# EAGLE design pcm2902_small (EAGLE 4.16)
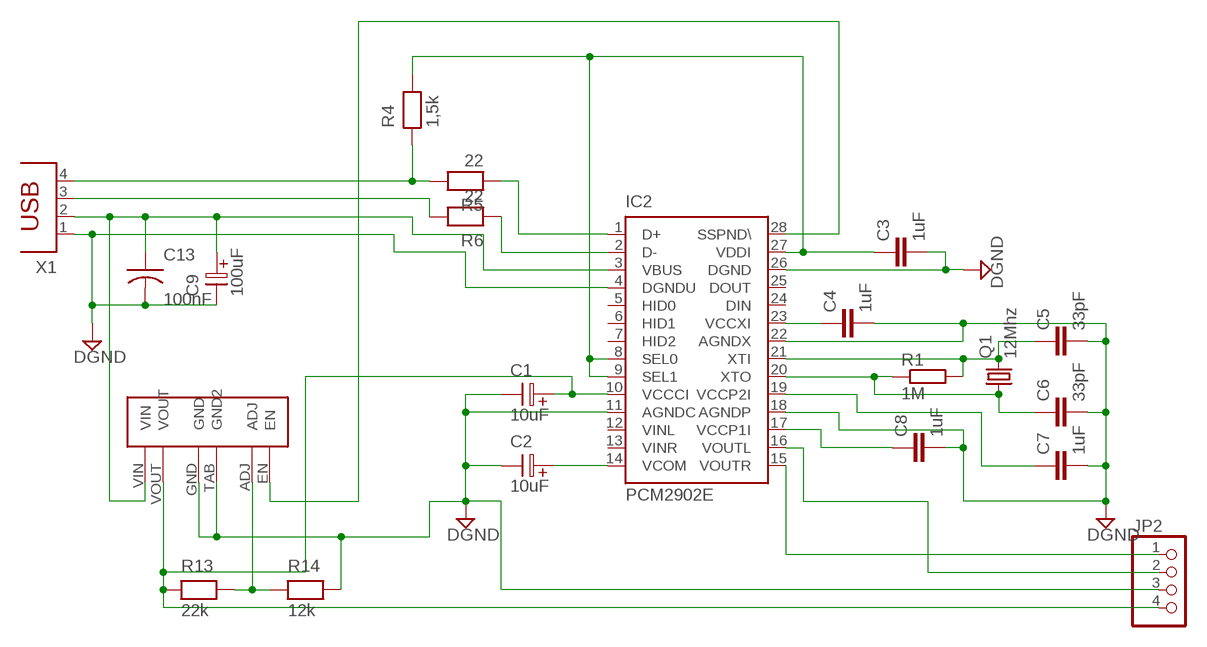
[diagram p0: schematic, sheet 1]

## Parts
C1  10uF  ELC-2,5L  [ES-2,5L]
C2  10uF  ELC-2,5L  [ES-2,5L]
C3  1uF  C-EUC1206  [C1206]
C4  1uF  C-EUC1206  [C1206]
C5  33pF  C-EUC1206  [C1206]
C6  33pF  C-EUC1206  [C1206]
C7  1uF  C-EUC1206  [C1206]
C8  1uF  C-EUC1206  [C1206]
C9  100uF  ELC-2,5L  [ES-2,5L]
C13  100nF  CAP-2,5  [C-2,5]
IC2  PCM2902E  [SSOP28DB]
JP2  PINHD-1X4  [1X04]
Q1  12Mhz  CRYTALHC49U-V  [HC49U-V]
R1  1M  R-EU_R1206  [R1206]
R4  1,5k  RESEU-5  [R-5]
R5  22  RESEU-5  [R-5]
R6  22  RESEU-5  [R-5]
R13  22k  RESEU-5  [R-5]
R14  12k  RESEU-5  [R-5]
U$2  REG102GA-A  [SOT223-5]
X1  PN87520  [PN87520]

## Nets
DGND: C1.2 C2.2 C3.2 C4.2 C5.2 C6.2 C7.2 C8.2 C9.2 C13.2 IC2.4(DGNDU) IC2.11(AGNDC) IC2.18(AGNDP) IC2.22(AGNDX) IC2.26(DGND) JP2.3 R14.2 U$2.GND U$2.TAB(GND2) X1.1
N$1: C2.1 IC2.14(VCOM)
N$2: C1.1 IC2.10(VCCCI) JP2.4 R13.1 U$2.VOUT
N$3: IC2.1(D+) R5.1
N$4: R4.1 R5.2 X1.4
N$5: R6.2 X1.3
N$6: IC2.2(D-) R6.1
N$8: C3.1 IC2.8(SEL0) IC2.9(SEL1) IC2.27(VDDI) R4.2
N$14: C4.1 IC2.23(VCCXI)
N$15: IC2.28(SSPND\) U$2.EN
N$18: C5.1 IC2.21(XTI) Q1.2 R1.2
N$19: C6.1 IC2.20(XTO) Q1.1 R1.1
N$20: C7.1 IC2.19(VCCP2I)
N$21: C8.1 IC2.17(VCCP1I)
N$24: IC2.16(VOUTL) JP2.2
N$25: IC2.15(VOUTR) JP2.1
N$26: R13.2 R14.1 U$2.ADJ
N$30: C9.1 C13.1 IC2.3(VBUS) U$2.VIN X1.2
Unconnected: IC2.5(HID0) IC2.6(HID1) IC2.7(HID2) IC2.12(VINL) IC2.13(VINR) IC2.24(DIN) IC2.25(DOUT)

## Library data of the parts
C1 C2 C9 = discrete:ELC-2,5L
C3-C8 = rcl:C-EU: CAPACITOR, European symbol
C13 = discrete:CAP-2,5
IC2 = texas:PCM290*: STEREO AUDIO CODEC WITH USB INTERFACE SINGLE-ENDED ANALOG INPUT/OUTPUT AND S/PDIF
JP2 = pinhead:PINHD-1X4: PIN HEADER
Q1 = crystal:CRYTAL: CRYSTAL
R1 = rcl:R-EU_: RESISTOR, European symbol
R4-R6 R13 R14 = discrete:RESEU-5
U$2 = Reg102:REG102GA-A
X1 = con-berg:PN87520: BERG USB connector

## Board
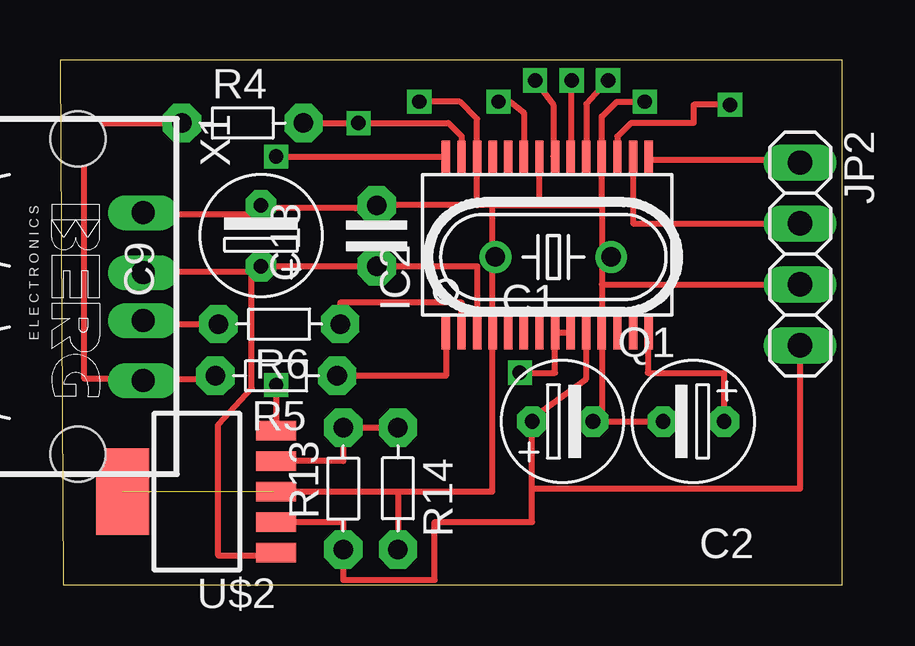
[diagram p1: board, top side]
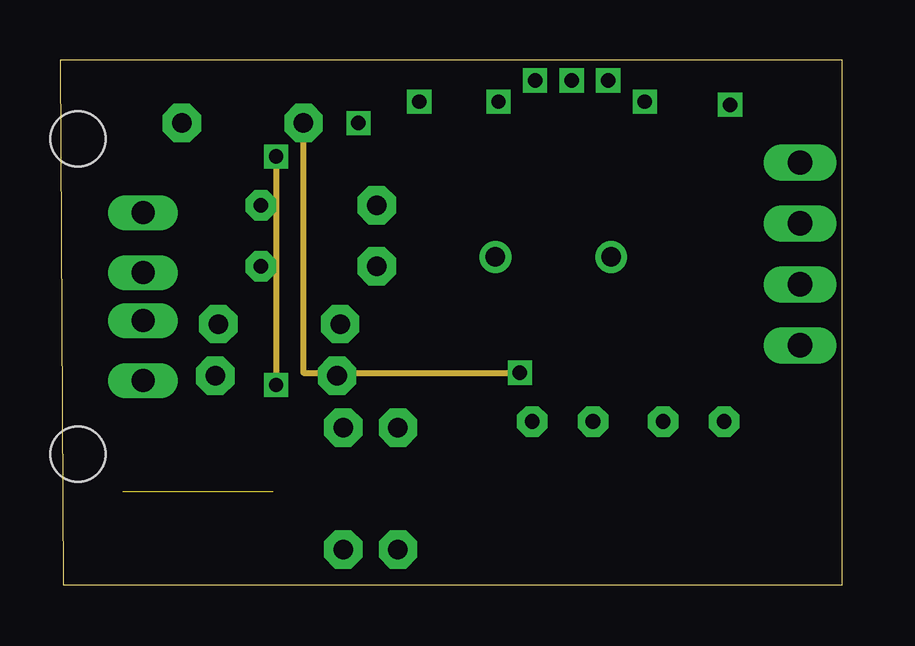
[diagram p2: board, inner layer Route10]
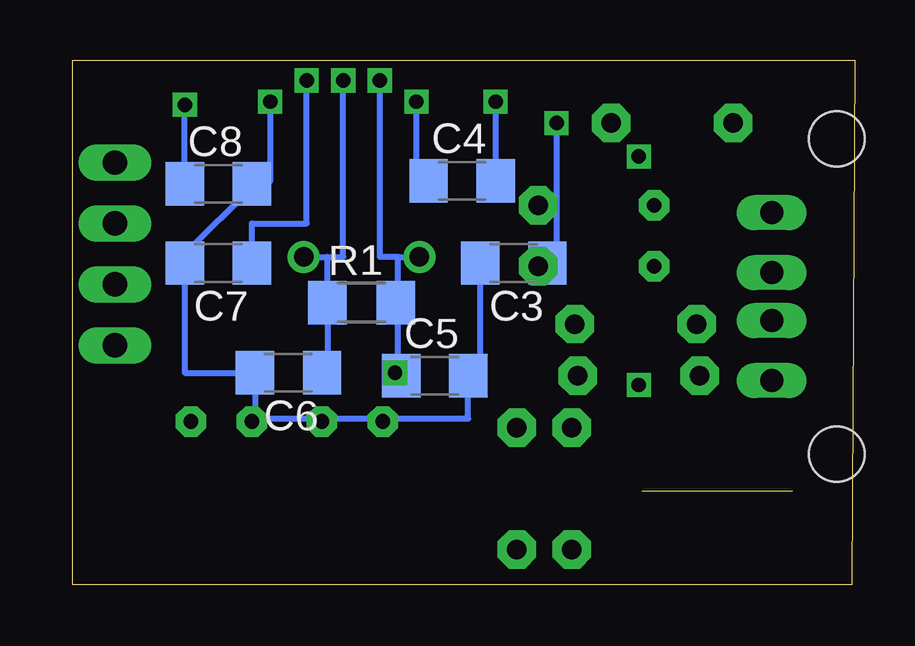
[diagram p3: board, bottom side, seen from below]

Size 32.62 x 21.89 mm. Coordinates in mm from the lower left corner, seen from the top.
Outline: 0.13,0 32.62,0 32.62,21.89 0,21.89 0.13,0
Copper layers (1*16): Top 0.035mm / dielectric 1.5mm / Bottom 0.035mm
Design rules "default": minimum track width 10mil, minimum drill 24mil, track to track 8mil, track to pad 8mil, pad to pad 8mil, via to via 8mil, smd to smd 8mil, copper to edge 40mil, drill to drill 8mil, minimum pad ring 10mil, minimum via ring 8mil, stop-mask expansion 4mil, vias tented up to drill 0mil, thermal gap 10mil

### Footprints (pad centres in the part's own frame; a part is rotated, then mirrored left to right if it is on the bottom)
ES-2,5L = drill 0.61 pad 1.27 octagon: 1 0,0; 2 2.54,0
C1206 = smd 1.6 x 1.8: 1 -1.4,0; 2 1.4,0
C-2,5 = drill 0.813 pad 1.6 octagon: 1 -1.27,0; 2 1.27,0
SSOP28DB = smd 0.348 x 1.397: 1 -4.225,-3.656; 2 -3.575,-3.656; 3 -2.925,-3.656; 4 -2.275,-3.656; 5 -1.625,-3.656; 6 -0.975,-3.656; 7 -0.325,-3.656; 8 0.325,-3.656; 9 0.975,-3.656; 10 1.625,-3.656; 11 2.275,-3.656; 12 2.925,-3.656; 13 3.575,-3.656; 14 4.225,-3.656; 15 4.225,3.656; 16 3.575,3.656; 17 2.925,3.656; 18 2.275,3.656; 19 1.625,3.656; 20 0.975,3.656; 21 0.325,3.656; 22 -0.325,3.656; 23 -0.975,3.656; 24 -1.625,3.656; 25 -2.275,3.656; 26 -2.925,3.656; 27 -3.575,3.656; 28 -4.225,3.656
1X04 = drill 1.016 long: 1 -3.81,0; 2 -1.27,0; 3 1.27,0; 4 3.81,0
HC49U-V = drill 0.813 round: 1 -2.413,0; 2 2.413,0
R1206 = smd 1.6 x 1.803: 1 -1.422,0; 2 1.422,0
R-5 = drill 0.813 pad 1.6 octagon: 1 -2.54,0; 2 2.54,0
SOT223-5 = smd 0.813 x 1.676: ADJ 1.27,-3.302; EN 2.54,-3.302; GND 0,-3.302; VIN -2.54,-3.302; VOUT -1.27,-3.302 | smd 3.6 x 2.2: TAB 0,3.099
PN87520 = drill 0.95 long: 1 -3.5,2.71; 2 -1,2.71; 3 1,2.71; 4 3.5,2.71 | hole 2.3: -6.57,0; 6.57,0

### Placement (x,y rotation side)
C1  19.68,6.82 0 top
C2  27.68,6.82 180 top
C3  14.22,13.42 180 bottom
C4  16.38,16.85 0 bottom
C5  17.52,8.73 0 bottom
C6  23.62,8.85 180 bottom
C7  26.54,13.42 180 bottom
C8  26.54,16.73 0 bottom
C9  8.38,13.3 90 top
C13  13.2,14.57 90 top
IC2  20.32,14.19 0 top
JP2  30.86,13.8 270 top
Q1  20.57,13.68 180 top
R1  20.57,11.77 0 bottom
R4  7.62,19.27 0 top
R5  9.01,8.73 180 top
R6  9.14,10.88 180 top
R13  11.81,4.03 90 top
R14  14.09,4.03 270 top
U$2  5.71,3.9 90 top
X1  0.76,12.03 270 top

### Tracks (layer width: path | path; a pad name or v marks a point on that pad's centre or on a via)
DGND  (via drill 0.6)  (1 unrouted)
  Top 0.254: 8.38,15.71 8.25,15.71 | 8.38,15.71 C9.2 8.38,15.46 3.47,15.46 X1.1 | 8.38,15.71 12.31,15.71 C13.2 17.39,15.84 | IC2.26 | 17.39,15.84 IC2.26 | 18.03,10.53 IC2.4 | 18.03,15.84 17.39,15.84 | 18.03,10.53 18.03,15.84 | 22.59,15.84 IC2.18 22.59,19.54 23.21,20.16 v24.38,20.16 | 18.03,15.84 19.93,15.84 | 19.93,15.84 22.59,15.84 | IC2.22 19.99,15.84 19.93,15.84 | IC2.26 17.39,19.44 16.68,20.16 v14.98,20.16 | 22.59,6.82 IC2.11 22.59,12.53 | 22.59,6.82 C1.2 | 22.59,6.82 C2.2 | 22.59,15.84 22.59,12.53 | 22.59,15.84 22.6,15.84 | 22.59,12.53 JP2.3 | 8.88,3.9 U$2.GND 14.09,3.9 | 18.03,10.53 18.03,3.9 14.09,3.9 | 14.09,3.9 R14.2
  Bottom 0.254: v24.38,20.16 24.38,16.85 25.01,16.85 | 24.68,16.98 25.4,16.85 25.01,16.85 | 27.93,11.01 27.93,8.85 C6.2 25.01,6.95 16.12,6.95 C5.2 | 27.93,11.01 27.94,10.63 | C4.2 14.98,16.6 v14.98,20.16 | 25.01,16.85 C8.2 25.01,16.73 27.93,13.8 C7.2 27.94,11.01 27.93,11.01 | C5.2 16.25,8.47 | C3.2 15.62,8.47 C5.2
N$1
  Top 0.254: IC2.14 24.51,10.53 24.51,8.85 27.68,8.85 C2.1
N$2
  Top 0.254: IC2.10 21.94,8.6 19.68,6.95 | U$2.VOUT 11.81,2.63 R13.1 11.81,0.22 15.62,0.22 15.62,2.63 19.68,2.63 19.68,4.03 | 19.68,6.95 C1.1 | 19.68,4.03 19.68,6.95 | JP2.4 30.86,4.03 19.68,4.03
N$3
  Top 0.254: IC2.1 16.09,8.73 R5.1
N$4
  Top 0.254: 3.47,8.6 3.42,8.6 | 3.47,8.6 X1.4 3.42,8.53 3.42,8.6 | R5.2 6.73,8.6 3.47,8.6 | R4.1 1.01,19.27 1.01,8.6 3.42,8.6
N$5
  Top 0.254: 6.85,10.88 R6.2 3.47,10.88 X1.3
N$6
  Top 0.254: IC2.2 16.74,11.77 11.68,11.77 R6.1
N$8  (via drill 0.6)
  Top 0.254: IC2.27 16.74,18.72 16.19,19.27 R4.2 v12.44,19.27 | 20.7,10.53 IC2.8 20.64,8.85 v19.17,8.85 | 20.7,10.53 IC2.9 | 20.7,10.53 20.7,10.5
  Route10 0.254: v19.17,8.85 10.15,8.85 R4.2
  Bottom 0.254: C3.1 12.44,13.42 v12.44,19.27
N$14  (via drill 0.6)
  Top 0.254: v18.28,20.16 18.75,20.16 19.34,19.69 IC2.23
  Bottom 0.254: C4.1 18.28,16.85 v18.28,20.16
N$15  (via drill 0.6)
  Top 0.254: IC2.28 9.01,17.84 v9.01,17.87 | v9.01,8.34 U$2.EN
  Route10 0.254: v9.01,17.87 v9.01,8.34
N$18  (via drill 0.6)
  Top 0.254: v19.81,21.04 20.57,20.03 20.57,17.87 20.64,17.87 IC2.21
  Bottom 0.254: 19.04,11.77 R1.2 | 19.04,13.68 Q1.2 | 19.04,11.77 19.04,13.68 | 19.04,9.23 19.04,8.34 | C5.1 19.04,9.23 | 19.04,9.23 19.04,11.77 | v19.81,21.04 19.81,13.68 19.04,13.68
N$19  (via drill 0.6)
  Top 0.254: 21.33,17.84 21.33,17.74 | IC2.20 21.33,17.84 | 21.33,17.84 v21.33,21.04
  Bottom 0.254: C6.1 21.97,8.47 21.97,11.77 R1.1 21.99,13.68 | Q1.1 21.99,13.68 | 21.99,13.68 21.33,13.68 v21.33,21.04
N$20  (via drill 0.6)
  Top 0.254: v22.86,21.04 22.88,21.09 21.94,20.06 IC2.19
  Bottom 0.254: C7.1 25.14,15.08 22.86,15.08 v22.86,21.04
N$21  (via drill 0.6)
  Top 0.254: IC2.17 23.24,18.7 23.8,19.27 26.41,19.27 26.41,20.03 v27.93,20.03
  Bottom 0.254: C8.1 v27.93,20.03
N$24
  Top 0.254: IC2.16 23.89,15.08 JP2.2
N$25
  Top 0.254: IC2.15 24.54,17.74 30.86,17.74 JP2.1
N$26
  Top 0.254: R14.1 R13.2 11.81,5.17 U$2.ADJ
N$30
  Top 0.254: X1.2 3.47,13.04 8,13.04 | IC2.3 17.39,13.3 C13.1 C9.1 8,13.17 8,13.04 | 9.01,1.1 U$2.VIN | 9.01,1.1 9.14,1.1 | 9.01,1.1 9.01,1.23 6.6,1.23 6.6,6.69 8,8.22 8,13.04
